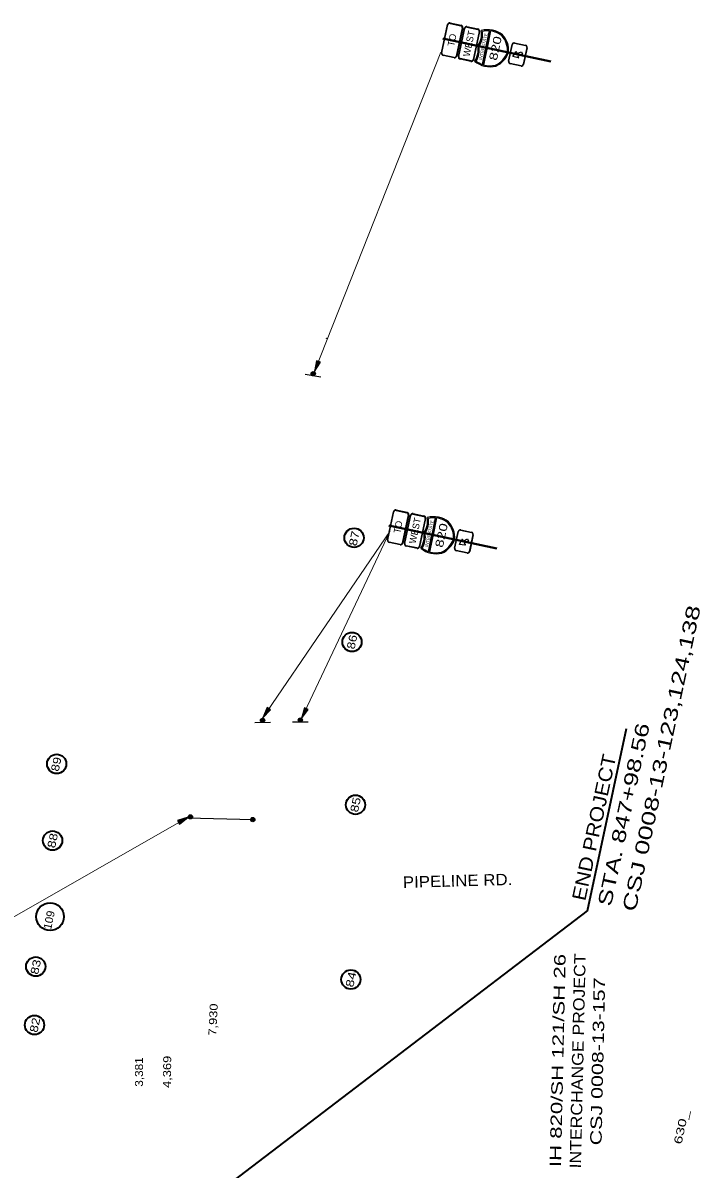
# Model space of a CAD drawing. Extents: x 2363411 to 2369702, y 6977197 to 6988655.
# Drawn here: x 2366110 to 2367294, y 6985397 to 6987401 of the extents above; entities that cross this region are included whole.
import ezdxf
from ezdxf.enums import TextEntityAlignment as Align

# ---------------------------------------------------------------- set-up
doc = ezdxf.new("R2010")
doc.units = 0
doc.header["$LTSCALE"] = 5.6
for name, color, linetype, lineweight in [('1', 7, 'Continuous', 25), ('13', 7, 'Continuous', 13), ('17', 7, 'Continuous', 35), ('25', 7, 'Continuous', 25), ('44', 7, 'Continuous', 25), ('48', 7, 'Continuous', 25), ('53', 7, 'Continuous', 40), ('55', 7, 'Continuous', 35)]:
    doc.layers.add(name, color=color, linetype=linetype, lineweight=lineweight)

msp = doc.modelspace()

# ---------------------------------------------------------------- hatches: boundary and pattern name
at = {"layer": '1'}
for points in [[(2366619.857, 6986791.341), (2366630.406, 6986807.777), (2366623.73, 6986810.489)], [(2366620.178, 6986790.688, 1), (2366615.696, 6986784.72, 1)], [(2366529.553, 6986185.894), (2366543.296, 6986199.771), (2366537.331, 6986203.815)], [(2366597.031, 6986185.269, 1), (2366593.655, 6986178.613, 1)], [(2366597.28, 6986184.672), (2366609.068, 6986200.244), (2366602.621, 6986203.464)], [(2366530.944, 6986184.611, 1), (2366527.719, 6986177.88, 1)], [(2366399.268, 6986012.095), (2366380.547, 6986006.518), (2366383.838, 6986000.119)], [(2366404.818, 6986016.037, 1), (2366401.549, 6986009.328, 1)], [(2366513.851, 6986011.243, 1), (2366510.582, 6986004.533, 1)]]:
    msp.add_hatch(color=256, dxfattribs=at).paths.add_polyline_path(points)

# ---------------------------------------------------------------- linework, layer by layer
for p, q in [((2366926.077, 6987387.45), (2366919.811, 6987358.112)), ((2366927.968, 6987387.239), (2366921.659, 6987357.72)), ((2366913.544, 6987328.776), (2366919.811, 6987358.112)), ((2366915.351, 6987328.176), (2366921.659, 6987357.72)), ((2366913.57, 6987328.571), (2366913.575, 6987328.581)), ((2366603.95, 6986786.791), (2366630.905, 6986782.039)), ((2366831.762, 6986535.64), (2366825.496, 6986506.302)), ((2366833.653, 6986535.429), (2366827.344, 6986505.91)), ((2366819.229, 6986476.966), (2366825.496, 6986506.302)), ((2366821.036, 6986476.366), (2366827.344, 6986505.91)), ((2366819.255, 6986476.761), (2366819.26, 6986476.771)), ((2366515.796, 6986177.606), (2366543.159, 6986178.236)), ((2366581.728, 6986178.609), (2366609.098, 6986178.617)), ((2366398.279, 6986011.053), (2366512.217, 6986007.888))]:
    msp.add_line(p, q, dxfattribs=at)
at = {"layer": '1', "lineweight": 13}
for p, q in [((2366840.992, 6987350.11), (2366619.857, 6986791.341)), ((2366751.714, 6986511.749), (2366529.421, 6986185.274)), ((2366751.714, 6986511.749), (2366597.28, 6986184.672)), ((2366399.268, 6986012.095), (2365740.837, 6985635.417))]:
    msp.add_line(p, q, dxfattribs=at)
at = {"layer": '1'}
for points in [[(2366913.575, 6987328.581), (2366919.839, 6987357.919), (2366926.107, 6987387.248)], [(2366927.969, 6987387.241), (2366921.66, 6987357.719), (2366915.352, 6987328.175)], [(2366819.26, 6986476.771), (2366825.524, 6986506.109), (2366831.792, 6986535.438)], [(2366833.653, 6986535.431), (2366827.344, 6986505.91), (2366821.037, 6986476.366)]]:
    msp.add_lwpolyline(points, dxfattribs=at)
for points in [[(2366619.857, 6986791.341), (2366630.406, 6986807.777), (2366623.73, 6986810.489)], [(2366529.553, 6986185.894), (2366543.296, 6986199.771), (2366537.331, 6986203.815)], [(2366597.28, 6986184.672), (2366609.068, 6986200.244), (2366602.621, 6986203.464)], [(2366399.268, 6986012.095), (2366380.547, 6986006.518), (2366383.838, 6986000.119)]]:
    msp.add_lwpolyline(points, close=True, dxfattribs=at)
for centre in [(2366617.937, 6986787.704), (2366595.343, 6986181.941), (2366529.332, 6986181.246), (2366403.183, 6986012.683), (2366512.217, 6986007.888)]:
    msp.add_circle(centre, 3.732, dxfattribs=at)
for centre, radius, start, end in [((2366922.763, 6987347.515), 41.954, 51.80216, 105.50453), ((2366876.107, 6987381.713), 35.984, 325.11936, 9.96967), ((2366876.107, 6987381.713), 37.874, 326.31727, 7.31411), ((2366876.136, 6987381.518), 37.876, 326.31755, 7.31439), ((2366922.763, 6987347.515), 40.064, 85.2486, 103.11335), ((2366922.794, 6987347.319), 40.066, 85.25606, 103.11363), ((2366922.761, 6987347.515), 40.066, 52.01897, 82.53095), ((2366922.763, 6987347.515), 40.064, 52.01869, 82.53068), ((2366918.77, 6987352.914), 38.81, 355.77729, 42.42367), ((2366918.771, 6987352.914), 38.808, 355.77701, 42.42339), ((2366918.771, 6987352.914), 40.698, 355.41087, 42.64677), ((2366870.275, 6987354.417), 35.984, 325.90827, 10.75858), ((2366870.275, 6987354.417), 37.874, 328.56383, 9.56067), ((2366870.304, 6987354.222), 37.876, 328.56411, 9.56095), ((2366920.981, 6987363.265), 38.81, 293.45483, 340.10121), ((2366920.983, 6987363.265), 38.808, 293.45455, 340.10093), ((2366920.983, 6987363.265), 40.698, 293.23117, 340.46707), ((2366926.833, 6987366.561), 41.954, 230.37341, 284.07578), ((2366926.833, 6987366.561), 40.064, 232.76459, 250.62934), ((2366926.863, 6987366.366), 40.066, 232.76486, 250.62547), ((2366926.833, 6987366.561), 40.064, 253.34726, 283.85925), ((2366926.831, 6987366.562), 40.066, 253.35167, 283.85953), ((2366781.792, 6986529.903), 35.984, 325.11936, 9.96967), ((2366781.792, 6986529.903), 37.874, 326.31727, 7.31411), ((2366781.82, 6986529.709), 37.876, 326.31755, 7.31439), ((2366828.447, 6986495.705), 41.954, 51.80216, 105.50453), ((2366828.447, 6986495.705), 40.064, 85.2486, 103.11335), ((2366828.478, 6986495.51), 40.066, 85.25606, 103.11363), ((2366828.446, 6986495.705), 40.066, 52.01897, 82.53095), ((2366828.447, 6986495.705), 40.064, 52.01869, 82.53068), ((2366824.454, 6986501.104), 38.81, 355.77729, 42.42367), ((2366824.456, 6986501.104), 38.808, 355.77701, 42.42339), ((2366824.456, 6986501.104), 40.698, 355.41087, 42.64677), ((2366775.96, 6986502.608), 35.984, 325.90827, 10.75858), ((2366775.96, 6986502.608), 37.874, 328.56383, 9.56067), ((2366775.988, 6986502.412), 37.876, 328.56411, 9.56095), ((2366826.666, 6986511.456), 38.81, 293.45483, 340.10121), ((2366826.667, 6986511.455), 38.808, 293.45455, 340.10093), ((2366826.667, 6986511.455), 40.698, 293.23117, 340.46707), ((2366832.517, 6986514.751), 41.954, 230.37341, 284.07578), ((2366832.517, 6986514.751), 40.064, 232.76459, 250.62934), ((2366832.548, 6986514.557), 40.066, 232.76486, 250.62547), ((2366832.517, 6986514.751), 40.064, 253.34726, 283.85925), ((2366832.516, 6986514.752), 40.066, 253.35167, 283.85953)]:
    msp.add_arc(centre, radius, start, end, dxfattribs=at)
at = {"layer": '17'}
for centre, radius in [((2366689.27, 6986500.798), 16.828), ((2366685.64, 6986318.57), 16.828), ((2366169.415, 6986105.288), 16.828), ((2366691.772, 6986033.857), 16.828), ((2366162.205, 6985971.186), 16.828), ((2366157.886, 6985838.108), 24.19), ((2366132.811, 6985750.828), 16.828), ((2366683.716, 6985728.24), 16.828), ((2366130.565, 6985648.61), 16.828)]:
    msp.add_circle(centre, radius, dxfattribs=at)
at = {"layer": '25'}
msp.add_circle((2366641.379, 6986849.84), 0.3, dxfattribs=at)
at = {"layer": '48'}
for p, q in [((2366842.046, 6987348.928), (2366852.587, 6987398.259)), ((2366842.797, 6987348.767), (2366853.338, 6987398.098)), ((2366842.797, 6987348.767), (2366853.338, 6987398.098)), ((2366856.984, 6987400.46), (2366876.067, 6987396.383)), ((2366856.984, 6987400.46), (2366876.067, 6987396.383)), ((2366857.144, 6987401.211), (2366876.227, 6987397.134)), ((2366878.429, 6987392.737), (2366867.888, 6987343.406)), ((2366878.429, 6987392.737), (2366867.888, 6987343.406)), ((2366879.18, 6987392.577), (2366868.64, 6987343.246)), ((2366871.573, 6987342.619), (2366882.114, 6987391.95)), ((2366872.324, 6987342.459), (2366882.865, 6987391.789)), ((2366872.324, 6987342.459), (2366882.865, 6987391.789)), ((2366886.511, 6987394.151), (2366905.594, 6987390.074)), ((2366886.511, 6987394.151), (2366905.594, 6987390.074)), ((2366886.671, 6987394.903), (2366905.754, 6987390.825)), ((2366907.956, 6987386.428), (2366897.416, 6987337.097)), ((2366907.956, 6987386.428), (2366897.416, 6987337.097)), ((2366908.707, 6987386.268), (2366898.167, 6987336.937)), ((2366959.15, 6987334.418), (2366965.395, 6987363.644)), ((2366959.901, 6987334.257), (2366966.146, 6987363.483)), ((2366959.901, 6987334.257), (2366966.146, 6987363.483)), ((2366969.792, 6987365.846), (2366988.875, 6987361.768)), ((2366969.792, 6987365.846), (2366988.875, 6987361.768)), ((2366969.953, 6987366.597), (2366989.035, 6987362.519)), ((2366991.237, 6987358.122), (2366984.992, 6987328.896)), ((2366991.237, 6987358.122), (2366984.992, 6987328.896)), ((2366991.988, 6987357.962), (2366985.744, 6987328.736)), ((2366864.082, 6987340.293), (2366844.999, 6987344.37)), ((2366864.242, 6987341.044), (2366845.16, 6987345.121)), ((2366864.242, 6987341.044), (2366845.16, 6987345.121)), ((2366893.609, 6987333.984), (2366874.526, 6987338.061)), ((2366893.769, 6987334.735), (2366874.687, 6987338.812)), ((2366893.769, 6987334.735), (2366874.687, 6987338.812)), ((2366981.186, 6987325.783), (2366962.103, 6987329.86)), ((2366981.346, 6987326.534), (2366962.264, 6987330.611)), ((2366981.346, 6987326.534), (2366962.264, 6987330.611)), ((2366762.668, 6986548.651), (2366781.751, 6986544.573)), ((2366762.668, 6986548.651), (2366781.751, 6986544.573)), ((2366762.829, 6986549.402), (2366781.911, 6986545.325)), ((2366747.731, 6986497.118), (2366758.271, 6986546.449)), ((2366748.482, 6986496.958), (2366759.022, 6986546.289)), ((2366748.482, 6986496.958), (2366759.022, 6986546.289)), ((2366784.113, 6986540.927), (2366773.573, 6986491.597)), ((2366784.113, 6986540.927), (2366773.573, 6986491.597)), ((2366784.864, 6986540.767), (2366774.324, 6986491.436)), ((2366777.258, 6986490.809), (2366787.798, 6986540.14)), ((2366778.009, 6986490.649), (2366788.549, 6986539.98)), ((2366778.009, 6986490.649), (2366788.549, 6986539.98)), ((2366792.195, 6986542.342), (2366811.278, 6986538.264)), ((2366792.195, 6986542.342), (2366811.278, 6986538.264)), ((2366792.356, 6986543.093), (2366811.438, 6986539.016)), ((2366813.64, 6986534.618), (2366803.1, 6986485.288)), ((2366813.64, 6986534.618), (2366803.1, 6986485.288)), ((2366814.391, 6986534.458), (2366803.851, 6986485.127)), ((2366864.835, 6986482.608), (2366871.079, 6986511.834)), ((2366865.586, 6986482.448), (2366871.83, 6986511.674)), ((2366865.586, 6986482.448), (2366871.83, 6986511.674)), ((2366875.477, 6986514.036), (2366894.559, 6986509.959)), ((2366875.477, 6986514.036), (2366894.559, 6986509.959)), ((2366875.637, 6986514.787), (2366894.72, 6986510.71)), ((2366769.766, 6986488.483), (2366750.684, 6986492.561)), ((2366769.927, 6986489.234), (2366750.844, 6986493.312)), ((2366769.927, 6986489.234), (2366750.844, 6986493.312)), ((2366799.454, 6986482.925), (2366780.371, 6986487.003)), ((2366799.454, 6986482.925), (2366780.371, 6986487.003)), ((2366896.922, 6986506.312), (2366890.677, 6986477.087)), ((2366896.922, 6986506.312), (2366890.677, 6986477.087)), ((2366897.673, 6986506.152), (2366891.428, 6986476.926)), ((2366799.293, 6986482.174), (2366780.211, 6986486.252)), ((2366886.87, 6986473.973), (2366867.788, 6986478.051)), ((2366887.031, 6986474.724), (2366867.948, 6986478.802)), ((2366887.031, 6986474.724), (2366867.948, 6986478.802))]:
    msp.add_line(p, q, dxfattribs=at)
at = {"layer": '48', "lineweight": 40}
for p, q in [((2366844.278, 6987374.243), (2367033.271, 6987333.861)), ((2366749.962, 6986522.433), (2366938.955, 6986482.051))]:
    msp.add_line(p, q, dxfattribs=at)
at = {"layer": '48'}
for points in [[(2366976.095, 6987340.381), (2366966.833, 6987342.617), (2366972.034, 6987350.505)], [(2366973.437, 6987350.181), (2366973.76, 6987347.625), (2366981.995, 6987350.866), (2366983.477, 6987347.102), (2366975.241, 6987343.862), (2366976.912, 6987341.58)], [(2366883.105, 6986488.102), (2366873.636, 6986489.156), (2366877.803, 6986497.635)], [(2366879.236, 6986497.491), (2366879.878, 6986494.995), (2366887.64, 6986499.246), (2366889.584, 6986495.698), (2366881.821, 6986491.448), (2366883.765, 6986489.395)]]:
    msp.add_lwpolyline(points, dxfattribs=at)
for centre, radius, start, end in [((2366856.342, 6987397.456), 3.84, 77.93906, 167.93906), ((2366856.342, 6987397.456), 3.072, 77.93906, 167.93906), ((2366856.342, 6987397.456), 3.072, 77.93906, 167.93906), ((2366875.425, 6987393.379), 3.072, 347.93906, 77.93906), ((2366875.425, 6987393.379), 3.072, 347.93906, 77.93906), ((2366875.425, 6987393.379), 3.84, 347.93906, 77.93906), ((2366885.869, 6987391.147), 3.84, 77.93906, 167.93906), ((2366885.869, 6987391.147), 3.072, 77.93906, 167.93906), ((2366885.869, 6987391.147), 3.072, 77.93906, 167.93906), ((2366904.952, 6987387.07), 3.072, 347.93906, 77.93906), ((2366904.952, 6987387.07), 3.072, 347.93906, 77.93906), ((2366904.952, 6987387.07), 3.84, 347.93906, 77.93906), ((2366845.802, 6987348.126), 3.84, 167.93906, 257.93906), ((2366845.802, 6987348.126), 3.072, 167.93906, 257.93906), ((2366845.802, 6987348.126), 3.072, 167.93906, 257.93906), ((2366969.15, 6987362.841), 3.84, 77.93906, 167.93906), ((2366969.15, 6987362.841), 3.072, 77.93906, 167.93906), ((2366969.15, 6987362.841), 3.072, 77.93906, 167.93906), ((2366972.677, 6987350.084), 0.767, 6.97844, 146.61705), ((2366988.233, 6987358.764), 3.072, 347.93906, 77.93906), ((2366988.233, 6987358.764), 3.072, 347.93906, 77.93906), ((2366988.233, 6987358.764), 3.84, 347.93906, 77.93906), ((2366864.884, 6987344.048), 3.84, 257.93906, 347.93906), ((2366864.884, 6987344.048), 3.072, 257.93906, 347.93906), ((2366864.884, 6987344.048), 3.072, 257.93906, 347.93906), ((2366875.329, 6987341.817), 3.84, 167.93906, 257.93906), ((2366875.329, 6987341.817), 3.072, 167.93906, 257.93906), ((2366875.329, 6987341.817), 3.072, 167.93906, 257.93906), ((2366894.411, 6987337.739), 3.84, 257.93906, 347.93906), ((2366894.411, 6987337.739), 3.072, 257.93906, 347.93906), ((2366894.411, 6987337.739), 3.072, 257.93906, 347.93906), ((2366962.906, 6987333.615), 3.84, 167.93906, 257.93906), ((2366962.906, 6987333.615), 3.072, 167.93906, 257.93906), ((2366962.906, 6987333.615), 3.072, 167.93906, 257.93906), ((2366976.285, 6987341.125), 0.767, 256.46542, 36.19399), ((2366981.988, 6987329.538), 3.84, 257.93906, 347.93906), ((2366981.988, 6987329.538), 3.072, 257.93906, 347.93906), ((2366981.988, 6987329.538), 3.072, 257.93906, 347.93906), ((2366762.026, 6986545.647), 3.84, 77.93906, 167.93906), ((2366762.026, 6986545.647), 3.072, 77.93906, 167.93906), ((2366762.026, 6986545.647), 3.072, 77.93906, 167.93906), ((2366781.109, 6986541.569), 3.072, 347.93906, 77.93906), ((2366781.109, 6986541.569), 3.072, 347.93906, 77.93906), ((2366781.109, 6986541.569), 3.84, 347.93906, 77.93906), ((2366791.553, 6986539.338), 3.84, 77.93906, 167.93906), ((2366791.553, 6986539.338), 3.072, 77.93906, 167.93906), ((2366791.553, 6986539.338), 3.072, 77.93906, 167.93906), ((2366810.636, 6986535.26), 3.072, 347.93906, 77.93906), ((2366810.636, 6986535.26), 3.072, 347.93906, 77.93906), ((2366810.636, 6986535.26), 3.84, 347.93906, 77.93906), ((2366874.835, 6986511.032), 3.84, 77.93906, 167.93906), ((2366874.835, 6986511.032), 3.072, 77.93906, 167.93906), ((2366874.835, 6986511.032), 3.072, 77.93906, 167.93906), ((2366893.917, 6986506.954), 3.072, 347.93906, 77.93906), ((2366893.917, 6986506.954), 3.072, 347.93906, 77.93906), ((2366893.917, 6986506.954), 3.84, 347.93906, 77.93906), ((2366751.486, 6986496.316), 3.84, 167.93906, 257.93906), ((2366751.486, 6986496.316), 3.072, 167.93906, 257.93906), ((2366751.486, 6986496.316), 3.072, 167.93906, 257.93906), ((2366770.569, 6986492.239), 3.84, 257.93906, 347.93906), ((2366770.569, 6986492.239), 3.072, 257.93906, 347.93906), ((2366770.569, 6986492.239), 3.072, 257.93906, 347.93906), ((2366781.013, 6986490.007), 3.84, 167.93906, 257.93906), ((2366781.013, 6986490.007), 3.072, 167.93906, 257.93906), ((2366781.013, 6986490.007), 3.072, 167.93906, 257.93906), ((2366878.494, 6986497.298), 0.767, 14.2014, 153.84001), ((2366883.199, 6986488.864), 0.767, 263.68838, 43.41695), ((2366800.096, 6986485.93), 3.84, 257.93906, 347.93906), ((2366800.096, 6986485.93), 3.072, 257.93906, 347.93906), ((2366800.096, 6986485.93), 3.072, 257.93906, 347.93906), ((2366868.59, 6986481.806), 3.84, 167.93906, 257.93906), ((2366868.59, 6986481.806), 3.072, 167.93906, 257.93906), ((2366868.59, 6986481.806), 3.072, 167.93906, 257.93906), ((2366887.673, 6986477.729), 3.84, 257.93906, 347.93906), ((2366887.673, 6986477.729), 3.072, 257.93906, 347.93906), ((2366887.673, 6986477.729), 3.072, 257.93906, 347.93906)]:
    msp.add_arc(centre, radius, start, end, dxfattribs=at)
at = {"layer": '55'}
for p, q in [((2367097.355, 6985848.386), (2367165.488, 6986167.26)), ((2366386.913, 6985306.514), (2367097.355, 6985848.386))]:
    msp.add_line(p, q, dxfattribs=at)

# ---------------------------------------------------------------- texts
at = {"layer": '1'}
for s, height, width, p in [('INTERSTATE', 5.198, 1.1, (2366912.663, 6987336.25)), ('820', 14.18, 1.35, (2366938.732, 6987334.5)), ('INTERSTATE', 5.198, 1.1, (2366818.348, 6986484.44)), ('820', 14.18, 1.35, (2366844.417, 6986482.69))]:
    msp.add_text(s, height=height, rotation=77.939, dxfattribs=dict(at, width=width)).set_placement(p)
at = {"layer": '13'}
for s, height, rotation, width, p in [('PIPELINE RD.', 20, 1.585, 1.1, (2366774.903, 6985888.319)), ('7,930', 14, 87.365, 1.2, (2366448.477, 6985629.744)), ('3,381', 14, 89.847, 1.1, (2366320.201, 6985540.648)), ('4,369', 14, 89.12, 1.2, (2366368.89, 6985538.482))]:
    msp.add_text(s, height=height, rotation=rotation, dxfattribs=dict(at, width=width)).set_placement(p)
at = {"layer": '17'}
for s, width, p in [('87', 1.25, (2366696.256, 6986498.173)), ('86', 1.2, (2366692.503, 6986317.192)), ('89', 1.2, (2366175.376, 6986103.328)), ('85', 1.25, (2366698.636, 6986032.48)), ('88', 1.25, (2366169.067, 6985969.807)), ('109', 1.05, (2366163.028, 6985830.792)), ('83', 1.25, (2366139.516, 6985748.708)), ('84', 1.3, (2366690.579, 6985726.862)), ('82', 1.25, (2366138.171, 6985647.073))]:
    msp.add_text(s, height=14, rotation=77.939, dxfattribs=dict(at, width=width)).set_placement(p, align=Align.CENTER)
at = {"layer": '44', "width": 1.45}
msp.add_text('  630_', height=14, rotation=77.939, dxfattribs=at).set_placement((2367274.31, 6985498.207), align=Align.RIGHT)
at = {"layer": '48'}
for s, p in [('TO', (2366866.325, 6987370.16)), ('WEST', (2366895.852, 6987363.851)), ('TO', (2366772.01, 6986518.35)), ('WEST', (2366801.537, 6986512.041))]:
    msp.add_text(s, height=11.82, rotation=77.859, dxfattribs=at).set_placement(p, align=Align.CENTER)
at = {"layer": '53'}
for s, width, p in [('IH 820/SH 121/SH 26', 1.45, (2367055.117, 6985586.316)), ('INTERCHANGE PROJECT', 1.15, (2367090.108, 6985585.542)), ('CSJ 0008-13-157', 1.4, (2367125.099, 6985584.768))]:
    msp.add_text(s, height=20, rotation=88.733, dxfattribs=dict(at, width=width)).set_placement(p, align=Align.CENTER)
at = {"layer": '55'}
for s, width, p in [('CSJ 0008-13-123,124,138', 1.45, (2367181.323, 6985845.678)), ('STA. 847+98.56', 1.4, (2367138.293, 6985854.872))]:
    msp.add_text(s, height=24, rotation=77.939, dxfattribs=dict(at, width=width)).set_placement(p)
at = {"layer": '55', "width": 1.15}
msp.add_text('END PROJECT', height=24, rotation=77.939, dxfattribs=at).set_placement((2367120.59, 6985991.84), align=Align.CENTER)

doc.saveas('drawing.dxf')
